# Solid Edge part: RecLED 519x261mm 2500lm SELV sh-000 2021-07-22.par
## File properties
Author: radoslaw.kuczynski
Template: iso metric part.par
Last saved by: radoslaw.kuczynski
Revision: 1
Application: Solid Edge
Gęstość: 0,000 kg/m^3
Dokładność: 0,990
Username: radoslaw.kuczynski
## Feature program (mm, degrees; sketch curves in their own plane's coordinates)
body "unnamed Body 1"
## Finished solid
Body 1: solid body, 4608 faces, 12217 edges, 8008 vertices, 3 separate solids.
  Faces by surface: plane 3669, cylinder 595, spline 161, swept 75, cone 52, torus 22, sphere 20, spun 14
  Edges by curve: line 10243, circle 1028, curve on surface 703, ellipse 132, spline 99, intersection 12
Bounding box of the edges (mm; curved faces can reach further): 519.000 x 4.500 x 261.000, from (-259.5, -3.5, -130.5) to (259.5, 1, 130.5).
Cylindrical faces by radius (mm): R0.2 x78, R0.2002 x4, R0.2169 x6, R0.25 x24, R0.3 x4, R0.3373 x6, R0.4 x16, R0.4006 x4, R0.4008 x4, R0.525 x4, R0.6 x24, R0.75 x1, R1 x14, R1.0894 x4, R1.1 x28, R1.7689 x1, R2.15 x15, R3 x3, R3.0012 x178, R3.05 x1, R5 x176
Conical faces (half-angle, radius in mm at the cone's reference point): 0.5 deg R0.5056 x8, 0.5 deg R1.0082 x8, 1 deg R0.5511 x4, 10 deg R0.2132 x4, 10 deg R0.4132 x4, 18.4844 deg R1.0657 x8, 27.363 deg R0.6214 x4, 45 deg R0.575 x4, 45 deg R0.625 x8
Toroidal faces (ring radius, tube radius in mm): R0.1 r0.2 x2, R0.8 r0.2 x8, R0.8522 r0.3 x4, R0.9002 r0.2 x2, R0.9018 r0.2 x2, R1.3 r0.2 x4
Spherical faces by radius (mm): R0.2 x16, R0.6 x4
Planar faces by outward normal: +x 496, +y 23, +z 511, -x 518, -y 593, -z 507, oblique 1021
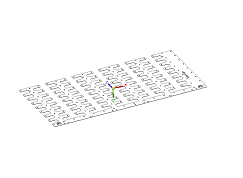
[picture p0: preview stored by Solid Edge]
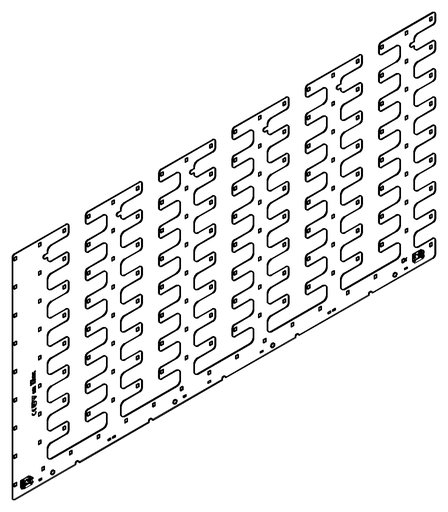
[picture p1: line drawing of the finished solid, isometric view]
